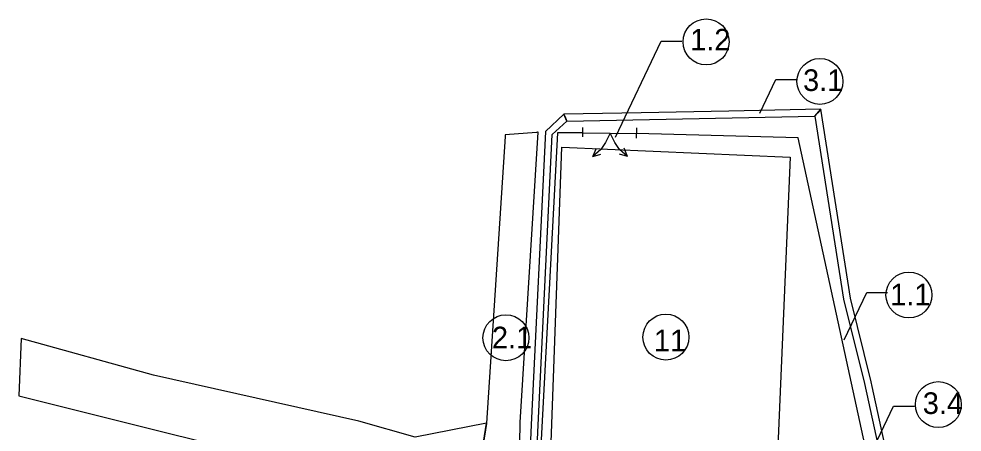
# Model space of a CAD drawing. Extents: x -438410 to -437811, y -1133174 to -1132817.
# Drawn here: x -438407.7 to -438325.9, y -1133054 to -1133018.2 of the extents above; entities that cross this region are included whole.
import ezdxf

# ---------------------------------------------------------------- set-up
doc = ezdxf.new("R2010")
doc.units = 0
for name, color, linetype in [('11 - bourané objekty', 7, 'Continuous'), ('12 - žlaby', 7, 'Continuous'), ('17 - panel', 7, 'Continuous'), ('19 - šotolina', 7, 'Continuous'), ('20 - popisy', 7, 'Continuous'), ('3 - ploty a brány', 7, 'Continuous')]:
    doc.layers.add(name, color=color, linetype=linetype)

msp = doc.modelspace()

# ---------------------------------------------------------------- linework, layer by layer
at = {"layer": '11 - bourané objekty'}
msp.add_lwpolyline([(-438360.783, -1133067.104), (-438361.974, -1133066.926), (-438360.619, -1133029.346), (-438340.823, -1133030.216), (-438342.346, -1133066.119)], close=True, dxfattribs=at)
at = {"layer": '12 - žlaby'}
for p, q in [((-438360.198, -1133027.086), (-438360.442, -1133026.495)), ((-438360.442, -1133026.495), (-438360.322, -1133026.786)), ((-438360.322, -1133026.786), (-438360.442, -1133026.495)), ((-438338.679, -1133026.673), (-438338.167, -1133026.063)), ((-438335.608, -1133042.43), (-438338.167, -1133026.063)), ((-438361.455, -1133028.259), (-438360.198, -1133027.086)), ((-438360.322, -1133026.786), (-438360.314, -1133026.786)), ((-438360.314, -1133026.805), (-438360.322, -1133026.786)), ((-438360.314, -1133026.786), (-438360.314, -1133026.805)), ((-438360.314, -1133026.805), (-438360.198, -1133027.086)), ((-438360.198, -1133027.086), (-438360.314, -1133026.805)), ((-438360.198, -1133027.086), (-438338.679, -1133026.673)), ((-438338.679, -1133026.673), (-438336.2, -1133042.523)), ((-438362.677, -1133053.437), (-438361.455, -1133028.259)), ((-438336.2, -1133042.523), (-438334.391, -1133049.825)), ((-438333.804, -1133049.696), (-438335.608, -1133042.43)), ((-438334.391, -1133049.825), (-438332.344, -1133059.164)), ((-438333.72, -1133050.083), (-438333.804, -1133049.696)), ((-438331.85, -1133058.606), (-438333.72, -1133050.084)), ((-438333.72, -1133050.084), (-438333.72, -1133050.084)), ((-438363.354, -1133068.817), (-438362.677, -1133053.437))]:
    msp.add_line(p, q, dxfattribs=at)
for points in [[(-438360.442, -1133026.495), (-438362.04, -1133027.991), (-438363.276, -1133053.408), (-438363.954, -1133068.796)], [(-438338.167, -1133026.063), (-438346.153, -1133026.218), (-438353.738, -1133026.365), (-438360.442, -1133026.495)], [(-438338.679, -1133026.673), (-438338.421, -1133026.366), (-438338.167, -1133026.063)], [(-438338.167, -1133026.063), (-438338.421, -1133026.366), (-438338.679, -1133026.673)], [(-438333.72, -1133050.084), (-438333.72, -1133050.083)]]:
    msp.add_lwpolyline(points, dxfattribs=at)
at = {"layer": '17 - panel'}
for p, q in [((-438364.235, -1133053.226), (-438362.688, -1133028.056)), ((-438362.688, -1133028.056), (-438362.737, -1133028.056)), ((-438365.553, -1133028.435), (-438367.16, -1133053.265)), ((-438365.543, -1133028.286), (-438365.544, -1133028.286)), ((-438365.544, -1133028.286), (-438365.544, -1133028.296)), ((-438365.544, -1133028.296), (-438365.544, -1133028.436)), ((-438367.16, -1133053.266), (-438367.16, -1133053.266)), ((-438364.244, -1133053.371), (-438364.244, -1133053.226))]:
    msp.add_line(p, q, dxfattribs=at)
for points in [[(-438362.737, -1133028.056), (-438362.834, -1133028.063), (-438365.543, -1133028.281)], [(-438365.544, -1133028.436), (-438365.553, -1133028.435)], [(-438365.543, -1133028.281), (-438365.543, -1133028.286)], [(-438367.16, -1133053.266), (-438367.164, -1133053.29), (-438369.534, -1133068.213)], [(-438367.16, -1133053.265), (-438367.16, -1133053.266)], [(-438364.63, -1133068.626), (-438364.248, -1133053.526), (-438364.244, -1133053.376), (-438364.244, -1133053.371)], [(-438364.244, -1133053.226), (-438364.235, -1133053.226)]]:
    msp.add_lwpolyline(points, dxfattribs=at)
at = {"layer": '19 - šotolina'}
msp.add_line((-438407.52, -1133045.926), (-438407.713, -1133050.896), dxfattribs=at)
msp.add_lwpolyline([(-438407.713, -1133050.896), (-438379.6, -1133057.917), (-438373.76, -1133060.703), (-438370.855, -1133064.441), (-438369.536, -1133068.226), (-438367.16, -1133053.265), (-438373.336, -1133054.497), (-438378.245, -1133053.104), (-438396.032, -1133049.116), (-438407.52, -1133045.926)], dxfattribs=at)
at = {"layer": '20 - popisy'}
for p, q in [((-438355.983, -1133028.477), (-438352.009, -1133020.147)), ((-438352.009, -1133020.147), (-438350.213, -1133020.147)), ((-438343.471, -1133026.41), (-438342.071, -1133023.474)), ((-438342.071, -1133023.474), (-438340.274, -1133023.474)), ((-438336.133, -1133046.042), (-438334.179, -1133041.947)), ((-438334.179, -1133041.947), (-438332.383, -1133041.947)), ((-438339.93, -1133068.724), (-438331.854, -1133051.795)), ((-438331.854, -1133051.795), (-438330.058, -1133051.795))]:
    msp.add_line(p, q, dxfattribs=at)
for centre in [(-438348.116, -1133020.217), (-438338.245, -1133023.645), (-438330.526, -1133042.163), (-438365.474, -1133045.874), (-438351.604, -1133045.814), (-438327.979, -1133051.654)]:
    msp.add_circle(centre, 1.991, dxfattribs=at)
at = {"layer": '3 - ploty a brány'}
for p, q in [((-438358.828, -1133027.628), (-438358.839, -1133028.453)), ((-438358.834, -1133028.106), (-438354.164, -1133028.168)), ((-438356.435, -1133028.142), (-438356.835, -1133028.942)), ((-438356.035, -1133028.942), (-438356.435, -1133028.142)), ((-438354.158, -1133027.664), (-438354.169, -1133028.562)), ((-438356.835, -1133028.942), (-438357.235, -1133029.542)), ((-438355.635, -1133029.542), (-438356.035, -1133028.942)), ((-438357.935, -1133030.142), (-438357.635, -1133029.442)), ((-438357.235, -1133029.542), (-438357.935, -1133030.142)), ((-438354.935, -1133030.142), (-438355.635, -1133029.542)), ((-438354.935, -1133030.142), (-438355.235, -1133029.442)), ((-438357.935, -1133030.142), (-438357.235, -1133029.942)), ((-438354.935, -1133030.142), (-438355.635, -1133029.942))]:
    msp.add_line(p, q, dxfattribs=at)
for points in [[(-438358.834, -1133028.106), (-438361.004, -1133028.096), (-438363.166, -1133068.824), (-438363.282, -1133072.553)], [(-438363.211, -1133079.96), (-438363.243, -1133080.683), (-438363.163, -1133083.782), (-438361.404, -1133100.856), (-438354.257, -1133103.589), (-438337.029, -1133101.059), (-438329.014, -1133079.716), (-438340.141, -1133028.533), (-438354.164, -1133028.163)]]:
    msp.add_lwpolyline(points, dxfattribs=at)

# ---------------------------------------------------------------- texts
at = {"layer": '20 - popisy'}
for s, p in [('1.2', (-438349.498, -1133020.967)), ('3.1', (-438339.707, -1133024.478)), ('1.1', (-438332.15, -1133043.058)), ('2.1', (-438366.686, -1133046.786)), ('11', (-438352.639, -1133047.034)), ('3.4', (-438329.327, -1133052.475))]:
    msp.add_text(s, height=1.875, dxfattribs=at).set_placement(p)

doc.saveas('drawing.dxf')
